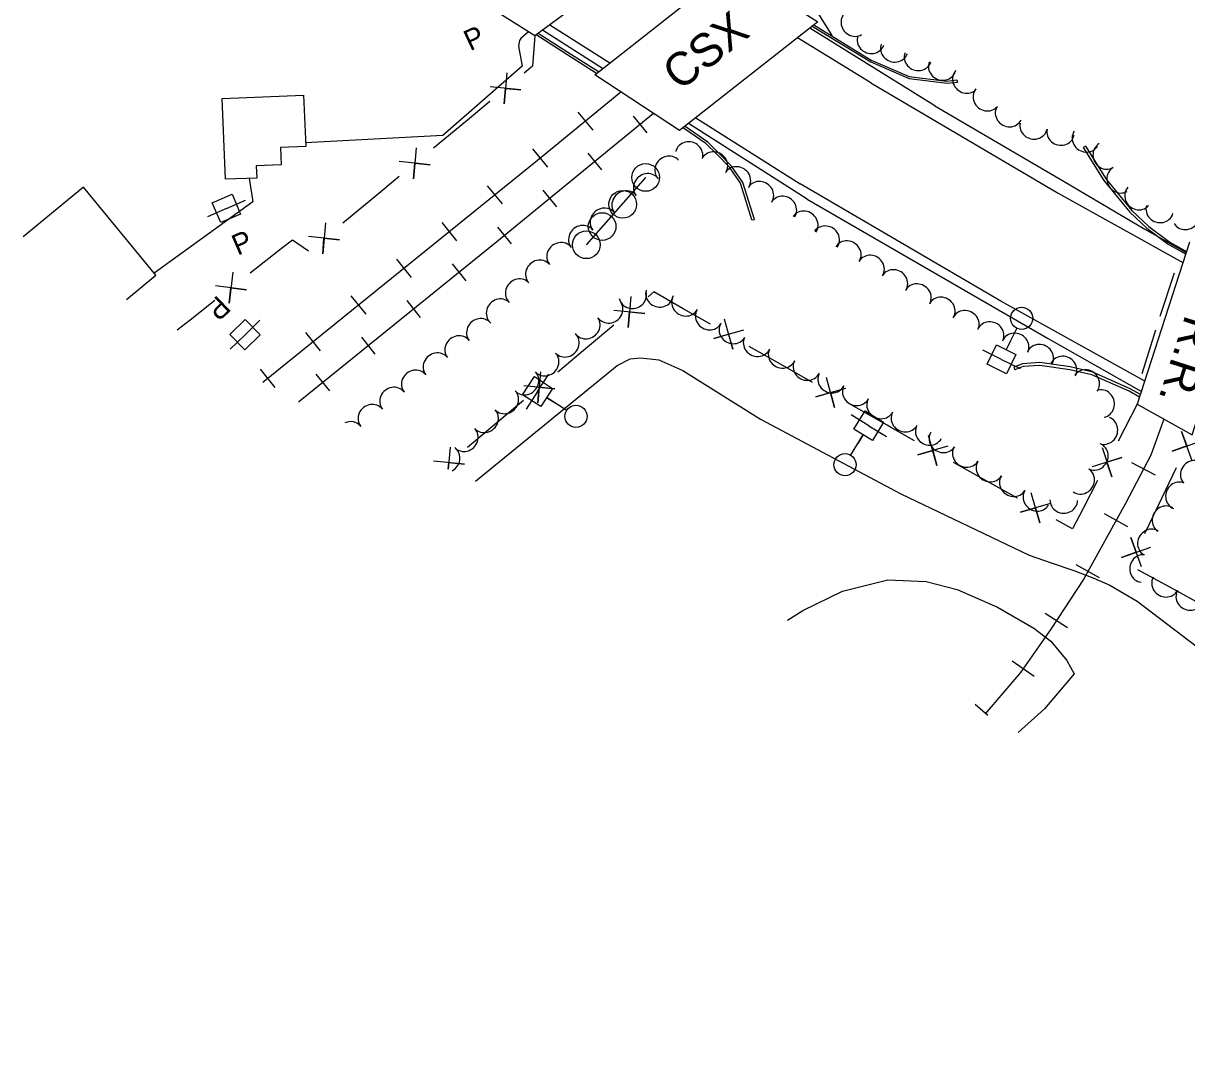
# Model space of a CAD drawing. Extents: x 1746010 to 1754829, y 655801 to 663091.
# Drawn here: x 1751643.3 to 1752063.6, y 658655.4 to 659030.7 of the extents above; entities that cross this region are included whole.
import ezdxf

# ---------------------------------------------------------------- set-up
doc = ezdxf.new("R2010")
doc.units = 0
for name, color, linetype in [('SURVEY - AERIAL SURVEY - Photo Control - Points - Elevations', 7, 'Continuous'), ('SURVEY - AERIAL SURVEY - Photo Control - Points - Locators', 7, 'Continuous'), ('SURVEY - AERIAL SURVEY - Photo Control - Points - Numbers', 7, 'Continuous'), ('SURVEY - AERIAL SURVEY - Photo Control with Text', 7, 'Continuous'), ('SURVEY - CENTERLINE - Existing Roads - Development', 7, 'Continuous'), ('SURVEY - CENTERLINE - Existing Roads Curve Text', 7, 'Continuous'), ('SURVEY - CENTERLINE - Existing Roads Text', 7, 'Continuous'), ('SURVEY - CONTROL - Points - Numbers', 7, 'Continuous')]:
    doc.layers.add(name, color=color, linetype=linetype)

msp = doc.modelspace()

# ---------------------------------------------------------------- linework, layer by layer
at = {"layer": 'SURVEY - AERIAL SURVEY - Photo Control - Points - Elevations'}
for points in [[(1751808.51, 659038.41), (1751858.64, 659075.74), (1751878.49, 659063.36), (1751828.11, 659026.2)], [(1751849.79, 659012.16), (1751899.19, 659051.12), (1751930.3, 659031.24), (1751880.29, 658991.94)], [(1751828.11, 659026.2), (1751808.51, 659038.41)], [(1751880.29, 658991.94), (1751849.79, 659012.16)], [(1752064.54, 658951.68), (1752045.7, 658893.16), (1752065.48, 658882.04), (1752084.32, 658940.56)]]:
    msp.add_lwpolyline(points, dxfattribs=at)
at = {"layer": 'SURVEY - AERIAL SURVEY - Photo Control - Points - Locators'}
for p, q in [((1751843.59, 658998.68), (1751848.99, 658992.11)), ((1751868.63, 658991.2), (1751863.69, 658997.23)), ((1751827.25, 658985.32), (1751832.65, 658978.76)), ((1751852.31, 658977.82), (1751847.37, 658983.85)), ((1751810.87, 658972.07), (1751816.22, 658965.47)), ((1751835.99, 658964.44), (1751831.05, 658970.47)), ((1751794.46, 658958.81), (1751799.81, 658952.2)), ((1751819.67, 658951.06), (1751814.73, 658957.09)), ((1751778.05, 658945.55), (1751783.4, 658938.94)), ((1751803.24, 658937.75), (1751798.37, 658943.84)), ((1751761.64, 658932.28), (1751766.98, 658925.68)), ((1751786.83, 658924.49), (1751781.96, 658930.58)), ((1751745.22, 658919.02), (1751750.57, 658912.41)), ((1751770.41, 658911.23), (1751765.54, 658917.32)), ((1751728.81, 658905.76), (1751734.16, 658899.15)), ((1751754, 658897.97), (1751749.13, 658904.06)), ((1752052.33, 658867.57), (1752043.7, 658872.03)), ((1752042.33, 658848.84), (1752033.82, 658853.53)), ((1752032.07, 658830.41), (1752023.56, 658835.1)), ((1752020.54, 658812.35), (1752012.37, 658817.62)), ((1752008.49, 658794.84), (1752000.5, 658800.37)), ((1751991.75, 658780.76), (1751987.16, 658784.67))]:
    msp.add_line(p, q, dxfattribs=at)
for points in [[(1751833.48, 659030.16), (1751855.15, 659016.39)], [(1751972.51, 659000.95), (1751927.4, 659028.97)], [(1751825.81, 659027.64), (1751823.04, 659025.26), (1751822.51, 659024.51), (1751822.21, 659022.47), (1751823.49, 659015.19), (1751794.79, 658990.25), (1751745.25, 658987.53)], [(1751852.57, 659014.35), (1751830.84, 659028.22)], [(1751949.41, 659009.23), (1751923.01, 659025.51)], [(1751949.41, 659009.23), (1752017.16, 658969.4), (1752062.18, 658944.38)], [(1751729.83, 658901.12), (1751829.04, 658981.29), (1751859.18, 659005.94)], [(1751972.51, 659000.95), (1752019.3, 658973.57), (1752048.4, 658956.34), (1752063.34, 658947.98)], [(1751870.94, 658998.14), (1751814.39, 658951.77), (1751742.72, 658893.87)], [(1751886.25, 658996.62), (1751923.86, 658972.71)], [(1751926.46, 658967.16), (1751883.59, 658994.54)], [(1751724.83, 658974.73), (1751726.19, 658966.21), (1751690.54, 658940.51)], [(1752048.37, 658901.45), (1751996.39, 658930.32), (1751923.86, 658972.71)], [(1751926.46, 658967.16), (1752013.3, 658917.01), (1752047.18, 658897.77)], [(1751806.65, 658865.38), (1751857.85, 658907.11), (1751862.53, 658909.51), (1751866.23, 658909.95), (1751872.83, 658909.13), (1751881.51, 658905.35), (1751909.59, 658887.71), (1751960.24, 658860.78), (1752006.69, 658838.66), (1752014.54, 658835.84), (1752022.81, 658833.1), (1752029.97, 658830.38), (1752035.76, 658827.86), (1752045.69, 658822.09), (1752067.35, 658805.52), (1752081.47, 658790.04), (1752100.04, 658764.68), (1752119.83, 658727.54), (1752122.27, 658725.09), (1752126.06, 658721.32), (1752174.99, 658694.08), (1752224.73, 658664.76), (1752243.16, 658655.36)], [(1752055.32, 658887.75), (1752050.57, 658874.7), (1752041.47, 658857.28), (1752026.34, 658830.11), (1752014.49, 658811.97), (1752003.53, 658796.22), (1751990.71, 658781.35)], [(1751919.35, 658815.14), (1751924.89, 658818.63), (1751939.2, 658825.64), (1751955.59, 658829.7), (1751969.49, 658829.08), (1751980.68, 658826.2), (1751995.16, 658819.91), (1752008.32, 658812.26), (1752014.49, 658807.59), (1752020.2, 658800.6), (1752022.85, 658795.74), (1752012.21, 658783.16), (1752002.67, 658774.62)]]:
    msp.add_lwpolyline(points, dxfattribs=at)
at = {"layer": 'SURVEY - AERIAL SURVEY - Photo Control - Points - Numbers'}
for points in [[(1751928.28, 659029.66), (1751949.41, 659016.74), (1751963.26, 659010.8), (1751977.04, 659009.04), (1751980.72, 659009.47)], [(1751928.88, 659030.12), (1751949.6, 659017.45), (1751963.25, 659011.56), (1751976.92, 659009.82), (1751980.5, 659010.26), (1751980.72, 659009.47)], [(1751850.4, 659012.63), (1751839.59, 659019.43), (1751828.6, 659026.57)], [(1751851.07, 659013.17), (1751840, 659020.14), (1751829.3, 659027.08)], [(1751906.51, 658959.68), (1751902.42, 658972.96), (1751898.34, 658978.78), (1751893.78, 658983.45), (1751889.84, 658987.31), (1751882.15, 658992.65), (1751881.62, 658992.98)], [(1751906.51, 658959.68), (1751907.37, 658959.87), (1751903.24, 658973.26), (1751899.11, 658979.16), (1751894.52, 658983.86), (1751890.52, 658987.79), (1751882.71, 658993.25), (1751882.29, 658993.52)], [(1752027, 658986.32), (1752026.15, 658985.91), (1752033.64, 658973.92), (1752043.03, 658962.49), (1752049.18, 658956.7), (1752056.88, 658950.97), (1752063.16, 658947.42)], [(1752027, 658986.32), (1752034.44, 658974.4), (1752043.74, 658963.06), (1752049.85, 658957.32), (1752057.45, 658951.68), (1752063.44, 658948.29)], [(1752046.82, 658896.65), (1752043.15, 658898.71), (1752029.62, 658904.72), (1752021.5, 658906.6), (1752010.54, 658908.19), (1752004.18, 658907.72), (1752001.07, 658906.49), (1752001.44, 658905.56)], [(1752046.51, 658895.69), (1752042.7, 658897.82), (1752029.31, 658903.77), (1752021.32, 658905.62), (1752010.52, 658907.19), (1752004.42, 658906.73), (1752001.44, 658905.56)]]:
    msp.add_lwpolyline(points, dxfattribs=at)
at = {"layer": 'SURVEY - AERIAL SURVEY - Photo Control with Text'}
for p, q in [((1751935.47, 659026.34), (1751927.53, 659039.06)), ((1751846.68, 658950.7), (1751868.12, 658975)), ((1751868.12, 658975), (1751868.12, 658975)), ((1751859.85, 658965.29), (1751859.85, 658965.29)), ((1751852.4, 658957.28), (1751852.4, 658957.28)), ((1751846.68, 658950.7), (1751846.68, 658950.7)), ((1752053.9, 658924.97), (1752059.1, 658940.58)), ((1752047.4, 658904.23), (1752052.35, 658920.02))]:
    msp.add_line(p, q, dxfattribs=at)
for centre in [(1751868.11, 658975.04), (1751859.84, 658965.33), (1751852.39, 658957.32), (1751846.67, 658950.73)]:
    msp.add_circle(centre, 5, dxfattribs=at)
at = {"layer": 'SURVEY - CENTERLINE - Existing Roads - Development'}
for points in [[(1751828.11, 659026.2), (1751827.24, 659015.19), (1751824.21, 659012.69)], [(1751817.98, 659012.85), (1751816.98, 659001.66), (1751817.44, 659007.22), (1751823.07, 659006.69), (1751811.89, 659007.82)], [(1751811.8, 659002.43), (1751803.01, 658995.17)], [(1751803.01, 658995.17), (1751791.45, 658985.62)], [(1751785.21, 658985.78), (1751784.21, 658974.59), (1751784.67, 658980.15), (1751790.3, 658979.62), (1751779.12, 658980.75)], [(1751779.03, 658975.36), (1751770.24, 658968.1)], [(1751680.58, 658931), (1751691.18, 658939.74), (1751664.99, 658971.51), (1751643.29, 658953.62)], [(1751770.24, 658968.1), (1751758.68, 658958.55)], [(1751752.44, 658958.71), (1751751.45, 658947.52), (1751751.91, 658953.08), (1751757.54, 658952.55), (1751746.35, 658953.68)], [(1751737.06, 658949.69), (1751725.23, 658940.46)], [(1751746.26, 658948.41), (1751740.55, 658952.41), (1751737.06, 658949.69)], [(1751719, 658940.8), (1751717.69, 658929.64), (1751718.31, 658935.19), (1751723.92, 658934.5), (1751712.77, 658935.94)], [(1751881.69, 658927.66), (1751871.08, 658933.73), (1751868.97, 658931.97)], [(1751712.54, 658930.56), (1751703.55, 658923.55)], [(1751862.73, 658932.1), (1751861.8, 658920.91), (1751862.23, 658926.47), (1751867.86, 658925.96), (1751856.67, 658927.04)], [(1751891.57, 658922.01), (1751881.69, 658927.66)], [(1751903.44, 658919.91), (1751892.7, 658916.9), (1751898.03, 658918.43), (1751899.55, 658912.98), (1751896.59, 658923.82)], [(1751703.55, 658923.55), (1751698.88, 658919.9)], [(1751856.61, 658921.66), (1751847.86, 658914.36)], [(1751847.86, 658914.36), (1751836.35, 658904.76)], [(1751918.51, 658906.6), (1751905.51, 658914.03)], [(1751830.11, 658904.89), (1751829.18, 658893.7), (1751829.61, 658899.26), (1751835.24, 658898.75), (1751824.05, 658899.83)], [(1751928.38, 658900.95), (1751918.51, 658906.6)], [(1751940.25, 658898.85), (1751929.52, 658895.84), (1751934.84, 658897.37), (1751936.36, 658891.92), (1751933.41, 658902.76)], [(1751823.99, 658894.45), (1751815.24, 658887.15)], [(1751955.32, 658885.54), (1751942.33, 658892.97)], [(1752045.7, 658893.16), (1752038.79, 658879.85)], [(1751815.24, 658887.15), (1751803.73, 658877.54)], [(1751965.27, 658879.97), (1751956.59, 658884.81), (1751955.32, 658885.54)], [(1751977.2, 658877.98), (1751966.45, 658874.88), (1751971.78, 658876.45), (1751973.34, 658871.03), (1751970.3, 658881.83)], [(1752065.53, 658872.77), (1752061.71, 658883.35), (1752063.64, 658878.1), (1752058.31, 658876.22), (1752068.93, 658879.9)], [(1751797.49, 658877.68), (1751796.83, 658869.76)], [(1752032.99, 658877.57), (1752036.45, 658866.88), (1752034.7, 658872.18), (1752040.09, 658873.89), (1752029.35, 658870.56)], [(1751796.81, 658869.76), (1751796.99, 658872.05), (1751802.62, 658871.54), (1751791.43, 658872.62)], [(1751992.42, 658864.82), (1751979.32, 658872.13)], [(1752053.35, 658856.76), (1752059.8, 658870.3)], [(1752031.38, 658865.57), (1752026.13, 658855.45)], [(1752002.38, 658859.27), (1751992.42, 658864.82)], [(1752014.31, 658857.28), (1752003.55, 658854.18), (1752008.89, 658855.75), (1752010.45, 658850.33), (1752007.41, 658861.12)], [(1752048.44, 658846.46), (1752053.35, 658856.76)], [(1752026.13, 658855.45), (1752022.33, 658848.14), (1752016.44, 658851.43)], [(1752047.23, 658834.41), (1752043.41, 658844.98), (1752045.34, 658839.74), (1752040.01, 658837.85), (1752050.63, 658841.54)], [(1752059.04, 658826.2), (1752045.86, 658833.35)], [(1752069.05, 658820.76), (1752059.04, 658826.2)]]:
    msp.add_lwpolyline(points, dxfattribs=at)
msp.add_lwpolyline([(1751715.17, 659003.56), (1751744.54, 659004.77), (1751745.31, 658986.23), (1751736.18, 658985.85), (1751736.44, 658979.6), (1751727.42, 658979.23), (1751727.6, 658974.84), (1751716.38, 658974.38)], close=True, dxfattribs=at)
at = {"layer": 'SURVEY - CENTERLINE - Existing Roads Curve Text'}
for p, q in [((1751716.67, 658963.86), (1751723.55, 658966.85)), ((1751716.67, 658963.86), (1751709.79, 658960.88)), ((1751723.4, 658918.26), (1751728.78, 658923.49)), ((1752002.2, 658920.67), (1751998.38, 658912.86)), ((1751723.4, 658918.26), (1751718.03, 658913.02)), ((1751998.55, 658913.22), (1751999.96, 658916.09)), ((1751996.66, 658909.35), (1751989.92, 658912.65)), ((1751996.66, 658909.35), (1752003.4, 658906.06)), ((1751829.07, 658897.71), (1751833.14, 658904.02)), ((1751829.07, 658897.71), (1751825, 658891.41)), ((1751839.65, 658890.88), (1751832.34, 658895.6)), ((1751832.68, 658895.38), (1751835.37, 658893.65)), ((1751948.7, 658885.4), (1751942.29, 658889.3)), ((1751942.15, 658874.63), (1751946.67, 658882.07)), ((1751948.7, 658885.4), (1751955.11, 658881.5)), ((1751946.47, 658881.72), (1751944.8, 658878.99))]:
    msp.add_line(p, q, dxfattribs=at)
for points in [[(1751711.54, 658965.89), (1751718.69, 658969), (1751721.8, 658961.84), (1751714.65, 658958.73)], [(1751728.92, 658918.18), (1751723.33, 658912.74), (1751717.89, 658918.33), (1751723.48, 658923.77)], [(1751991.44, 658907.57), (1751994.87, 658914.57), (1752001.88, 658911.14), (1751998.45, 658904.14)], [(1751827.91, 658903.11), (1751834.46, 658898.88), (1751830.23, 658892.32), (1751823.67, 658896.55)], [(1751954.06, 658886.7), (1751950.01, 658880.04), (1751943.34, 658884.09), (1751947.4, 658890.76)]]:
    msp.add_lwpolyline(points, close=True, dxfattribs=at)
for centre in [(1752003.91, 658924.18), (1751842.93, 658888.77), (1751940.13, 658871.3)]:
    msp.add_circle(centre, 4, dxfattribs=at)
at = {"layer": 'SURVEY - CENTERLINE - Existing Roads Text'}
for centre, major_axis, start_param, end_param in [((1751943.46, 659030.89), (-2.65, 4.24), 0, 3.141593), ((1751949.45, 659024.52), (-4.7, 1.7), 0, 3.141593), ((1751957.93, 659021.44), (-4.7, 1.7), 0, 3.141593), ((1751966.42, 659018.37), (-4.7, 1.7), 0, 3.141593), ((1751975.22, 659014.87), (-4.59, 1.97), 0, 3.141593), ((1751983.83, 659010.27), (-3.7, 3.36), 0, 3.141593), ((1751991.29, 659003.87), (-3.87, 3.16), 0, 3.141593), ((1751999.34, 658998.09), (-4.43, 2.32), 0, 3.141593), ((1752008.25, 658993.58), (-4.88, 1.1), 0, 3.141593), ((1752018, 658991.38), (-4.88, 1.1), 0, 3.141593), ((1752027.08, 658988.99), (-4.19, 2.73), 0, 3.141593), ((1751883.78, 658983.19), (4.83, -1.28), 0, 3.141593), ((1752034.45, 658982.94), (-2.53, 4.31), 0, 3.141593), ((1751876.28, 658977.93), (3.67, 3.4), 0, 3.141593), ((1751892.84, 658979.49), (4.21, -2.7), 0, 3.141593), ((1751901.14, 658974.15), (4.21, -2.7), 0, 3.141593), ((1752039.5, 658974.33), (-2.53, 4.31), 0, 3.141593), ((1751868.6, 658971.62), (3.91, 3.12), 0, 3.141593), ((1751909.45, 658968.82), (4.21, -2.7), 0, 3.141593), ((1751860.78, 658965.39), (3.91, 3.12), 0, 3.141593), ((1752046.01, 658968.18), (-3.75, 3.31), 0, 3.141593), ((1751917.75, 658963.48), (4.21, -2.7), 0, 3.141593), ((1751852.96, 658959.16), (3.91, 3.12), 0, 3.141593), ((1751925.48, 658958.1), (4.11, -2.86), 0, 3.141593), ((1752053.81, 658963.46), (-4.78, 1.48), 0, 3.141593), ((1752063.27, 658961.01), (-4.31, -2.54), 0, 3.141593), ((1751845.14, 658952.92), (3.91, 3.12), 0, 3.141593), ((1751933.21, 658952.73), (4.11, -2.86), 0, 3.141593), ((1751837.28, 658946.74), (3.95, 3.07), 0, 3.141593), ((1751941.02, 658947.37), (4.25, -2.63), 0, 3.141593), ((1751829.58, 658940.37), (3.72, 3.34), 0, 3.141593), ((1751949.44, 658942.16), (4.25, -2.63), 0, 3.141593), ((1751957.87, 658936.96), (4.25, -2.63), 0, 3.141593), ((1751822.27, 658933.56), (3.45, 3.62), 0, 3.141593), ((1751966.35, 658931.84), (4.37, -2.43), 0, 3.141593), ((1751863.44, 658932.44), (-4.86, -1.16), 0, 3.141593), ((1751873.07, 658932.94), (-4.8, 1.41), 0, 3.141593), ((1751882.41, 658929.78), (-4.32, 2.52), 0, 3.141593), ((1751974.98, 658927.03), (4.37, -2.43), 0, 3.141593), ((1751815.37, 658926.31), (3.45, 3.62), 0, 3.141593), ((1751855, 658927.24), (-4.11, -2.84), 0, 3.141593), ((1751808.29, 658919.28), (3.92, 3.1), 0, 3.141593), ((1751846.77, 658921.56), (-4.11, -2.84), 0, 3.141593), ((1751890.99, 658924.78), (-4.32, 2.52), 0, 3.141593), ((1751983.62, 658922.24), (4.55, -2.07), 0, 3.141593), ((1751899.56, 658919.79), (-4.32, 2.52), 0, 3.141593), ((1751992.59, 658918.16), (4.55, -2.07), 0, 3.141593), ((1751800.45, 658913.07), (3.92, 3.1), 0, 3.141593), ((1751839.23, 658915.04), (-3.65, -3.42), 0, 3.141593), ((1751908.33, 658915.14), (-4.53, 2.12), 0, 3.141593), ((1752001.57, 658914.08), (4.55, -2.07), 0, 3.141593), ((1752010.52, 658909.98), (4.46, -2.26), 0, 3.141593), ((1751792.61, 658906.87), (3.92, 3.1), 0, 3.141593), ((1751831.94, 658908.22), (-3.65, -3.42), 0, 3.141593), ((1751917.35, 658910.93), (-4.53, 2.12), 0, 3.141593), ((1751926.3, 658906.53), (-4.46, 2.26), 0, 3.141593), ((1752018.96, 658905.71), (4.46, -2.26), 0, 3.141593), ((1751784.77, 658900.66), (3.92, 3.1), 0, 3.141593), ((1751824.65, 658901.4), (-3.65, -3.42), 0, 3.141593), ((1751935.22, 658902.01), (-4.46, 2.26), 0, 3.141593), ((1752027.19, 658900.79), (4.01, -2.98), 0, 3.141593), ((1751776.93, 658894.46), (3.92, 3.1), 0, 3.141593), ((1751944.12, 658897.45), (-4.4, 2.38), 0, 3.141593), ((1752032.74, 658893.36), (0.97, -4.91), 0, 3.141593), ((1751817.36, 658894.58), (-3.65, -3.42), 0, 3.141593), ((1751952.91, 658892.68), (-4.4, 2.38), 0, 3.141593), ((1751769.09, 658888.26), (3.92, 3.1), 0, 3.141593), ((1751810.06, 658887.76), (-3.65, -3.42), 0, 3.141593), ((1751961.7, 658887.91), (-4.4, 2.38), 0, 3.141593), ((1751761.25, 658882.05), (3.92, 3.1), 0, 1.3091), ((1752033.89, 658883.62), (-1.71, -4.7), 0, 3.141593), ((1751802.77, 658880.94), (-3.65, -3.42), 0, 3.141593), ((1751970.49, 658883.14), (-4.4, 2.38), 0, 3.141593), ((1751975.38, 658880.45), (-4.25, 2.64), 0, 3.141593), ((1751983.87, 658875.18), (-4.25, 2.64), 0, 3.141593), ((1752030.4, 658874.26), (-2.38, -4.4), 0, 3.141593), ((1751796.2, 658873.43), (-3.28, -3.77), 1.180276, 3.141593), ((1752066.15, 658868.04), (3.79, 3.26), 0, 3.141593), ((1751992.36, 658869.9), (-4.25, 2.64), 0, 3.141593), ((1752025.43, 658865.6), (-2.86, -4.11), 0, 3.141593), ((1752000.85, 658864.63), (-4.25, 2.64), 0, 3.141593), ((1752060.68, 658860.1), (1.96, 4.6), 0, 3.141593), ((1752009.35, 658859.35), (-4.25, 2.64), 0, 3.141593), ((1752019.15, 658858.5), (-5, 0.1), 0, 3.141593), ((1752055.85, 658851.51), (2.72, 4.2), 0, 3.141593), ((1752050.6, 658843.11), (2.62, 4.26), 0, 3.141593), ((1752047.67, 658833.81), (0.6, 4.96), 0, 3.141593), ((1752055.83, 658828.29), (-4.39, 2.4), 0, 3.141593), ((1752064.6, 658823.5), (-4.39, 2.4), 0, 3.141593)]:
    msp.add_ellipse(centre, major_axis=major_axis, ratio=0.940188, start_param=start_param, end_param=end_param, dxfattribs=at)

# ---------------------------------------------------------------- texts
at = {"layer": 'SURVEY - CENTERLINE - Existing Roads Curve Text'}
for rotation, p in [(25.2934, (1751804.71, 659020.58)), (23.4845, (1751720.72, 658946.76)), (224.2356, (1751713.56, 658932.82))]:
    msp.add_text('P', height=7.48, rotation=rotation, dxfattribs=at).set_placement(p)
at = {"layer": 'SURVEY - CONTROL - Points - Numbers'}
for s, rotation, p in [('CSX', 38.1634, (1751880.37, 659005.99)), ('R.R.', 252.1557, (1752063.17, 658925.81))]:
    msp.add_text(s, height=12, rotation=rotation, dxfattribs=at).set_placement(p)

doc.saveas('drawing.dxf')
